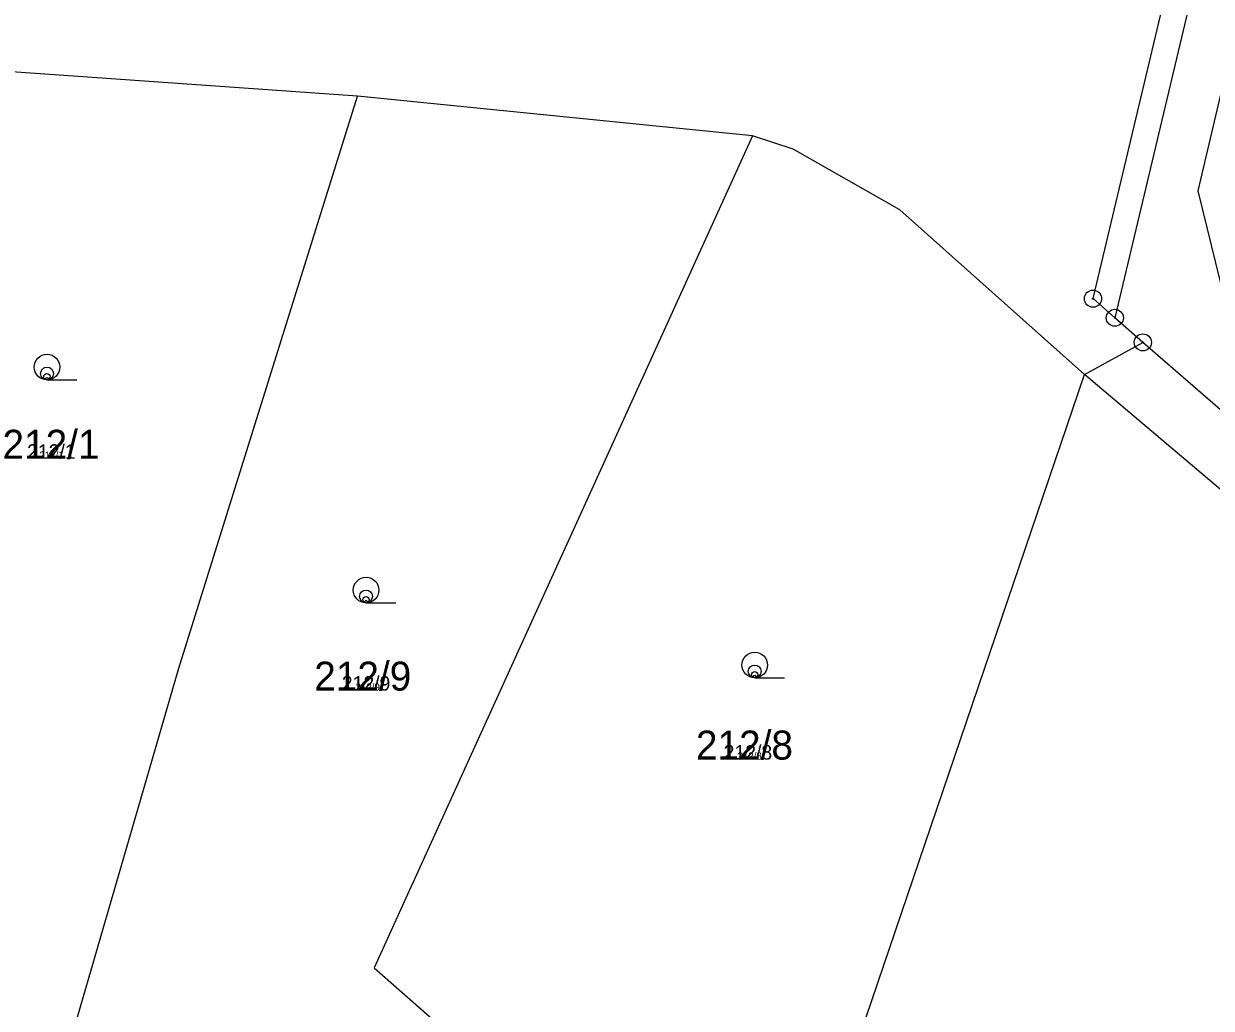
# Model space of a CAD drawing. Extents: x -744652 to -739090, y -980828 to -975855.
# Drawn here: x -742178.7 to -742109.1, y -978683.6 to -978626 of the extents above; entities that cross this region are included whole.
import ezdxf

# ---------------------------------------------------------------- set-up
doc = ezdxf.new("R2010")
doc.units = 0
for name, color, linetype in [('KAT_02_hranice parcel', 7, 'Continuous'), ('KAT_03_1000_čísla parcelní', 7, 'Continuous'), ('KAT_03_100_čísla parcelní', 7, 'Continuous'), ('KAT_03_250_čísla parcelní', 7, 'Continuous'), ('KAT_03_500_čísla parcelní', 7, 'Continuous'), ('KAT_05_1000_značky kultur', 7, 'Continuous'), ('KAT_05_100_značky kultur', 7, 'Continuous'), ('KAT_05_250_značky kultur', 7, 'Continuous'), ('KAT_05_500_značky kultur', 7, 'Continuous'), ('KAT_11_značky bodu BP', 7, 'Continuous')]:
    doc.layers.add(name, color=color, linetype=linetype)

msp = doc.modelspace()

# ---------------------------------------------------------------- linework, layer by layer
at = {"layer": 'KAT_02_hranice parcel'}
for p, q in [((-742159.17, -978630.2), (-742186.86, -978628.26)), ((-742136.02, -978632.54), (-742159.17, -978630.2)), ((-742113.14, -978644.63), (-742114.78, -978643.19)), ((-742116.55, -978646.51), (-742113.14, -978644.63)), ((-742106.24, -978650.63), (-742113.14, -978644.63)), ((-742131.55, -978690.59), (-742116.55, -978646.51)), ((-742079.34, -978678.02), (-742116.55, -978646.51))]:
    msp.add_line(p, q, dxfattribs=at)
for points in [[(-742070.3, -978456.16), (-742079.78, -978496.02), (-742114.78, -978643.19)], [(-742114.78, -978643.19), (-742116.06, -978642.07), (-742109.22, -978613.32), (-742139.53, -978602.6)], [(-742106.24, -978650.63), (-742109.89, -978635.76), (-742106.79, -978622.55)], [(-742175.59, -978684.22), (-742169.64, -978663.71), (-742159.17, -978630.2)], [(-742136.02, -978632.54), (-742158.19, -978681.26), (-742148.13, -978690.11)], [(-742116.55, -978646.51), (-742127.39, -978636.86), (-742133.63, -978633.31), (-742136.02, -978632.54)]]:
    msp.add_lwpolyline(points, dxfattribs=at)
at = {"layer": 'KAT_05_1000_značky kultur'}
for p, q in [((-742177.363, -978646.83), (-742175.613, -978646.83)), ((-742158.663, -978659.89), (-742156.913, -978659.89)), ((-742135.883, -978664.28), (-742134.133, -978664.28))]:
    msp.add_line(p, q, dxfattribs=at)
for centre in [(-742177.363, -978646.08), (-742158.663, -978659.14), (-742135.883, -978663.53)]:
    msp.add_circle(centre, 0.75, dxfattribs=at)
at = {"layer": 'KAT_05_100_značky kultur'}
for p, q in [((-742177.369, -978646.83), (-742177.194, -978646.83)), ((-742158.669, -978659.89), (-742158.494, -978659.89)), ((-742135.889, -978664.28), (-742135.714, -978664.28))]:
    msp.add_line(p, q, dxfattribs=at)
for centre in [(-742177.369, -978646.755), (-742158.669, -978659.815), (-742135.889, -978664.205)]:
    msp.add_circle(centre, 0.075, dxfattribs=at)
at = {"layer": 'KAT_05_250_značky kultur'}
for p, q in [((-742177.368, -978646.83), (-742176.931, -978646.83)), ((-742158.668, -978659.89), (-742158.231, -978659.89)), ((-742135.888, -978664.28), (-742135.451, -978664.28))]:
    msp.add_line(p, q, dxfattribs=at)
for centre in [(-742177.368, -978646.642), (-742158.668, -978659.702), (-742135.888, -978664.092)]:
    msp.add_circle(centre, 0.187, dxfattribs=at)
at = {"layer": 'KAT_05_500_značky kultur'}
for p, q in [((-742177.367, -978646.83), (-742176.492, -978646.83)), ((-742158.667, -978659.89), (-742157.792, -978659.89)), ((-742135.887, -978664.28), (-742135.012, -978664.28))]:
    msp.add_line(p, q, dxfattribs=at)
for centre in [(-742177.366, -978646.455), (-742158.666, -978659.515), (-742135.886, -978663.905)]:
    msp.add_circle(centre, 0.375, dxfattribs=at)
at = {"layer": 'KAT_11_značky bodu BP'}
for centre, radius in [((-742116.06, -978642.07), 0.5), ((-742116.06, -978642.07), 0.0303), ((-742114.78, -978643.19), 0.5), ((-742114.78, -978643.19), 0.0303), ((-742113.14, -978644.63), 0.5), ((-742113.14, -978644.63), 0.0303)]:
    msp.add_circle(centre, radius, dxfattribs=at)

# ---------------------------------------------------------------- texts
at = {"layer": 'KAT_03_1000_čísla parcelní'}
for s, p in [('212/1', (-742179.973, -978651.45)), ('212/9', (-742161.703, -978665.03)), ('212/8', (-742139.333, -978669.07))]:
    msp.add_text(s, height=1.7, dxfattribs=at).set_placement(p)
at = {"layer": 'KAT_03_100_čísla parcelní'}
for s, p in [('212/1', (-742177.377, -978651.45)), ('212/9', (-742158.794, -978665.03)), ('212/8', (-742136.406, -978669.07))]:
    msp.add_text(s, height=0.17, dxfattribs=at).set_placement(p)
at = {"layer": 'KAT_03_250_čísla parcelní'}
for s, p in [('212/1', (-742177.81, -978651.45)), ('212/9', (-742159.279, -978665.03)), ('212/8', (-742136.894, -978669.07))]:
    msp.add_text(s, height=0.425, dxfattribs=at).set_placement(p)
at = {"layer": 'KAT_03_500_čísla parcelní'}
for s, p in [('212/1', (-742178.531, -978651.45)), ('212/9', (-742160.087, -978665.03)), ('212/8', (-742137.707, -978669.07))]:
    msp.add_text(s, height=0.85, dxfattribs=at).set_placement(p)

doc.saveas('drawing.dxf')
